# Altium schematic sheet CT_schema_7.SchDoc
size 274 x 160 mm
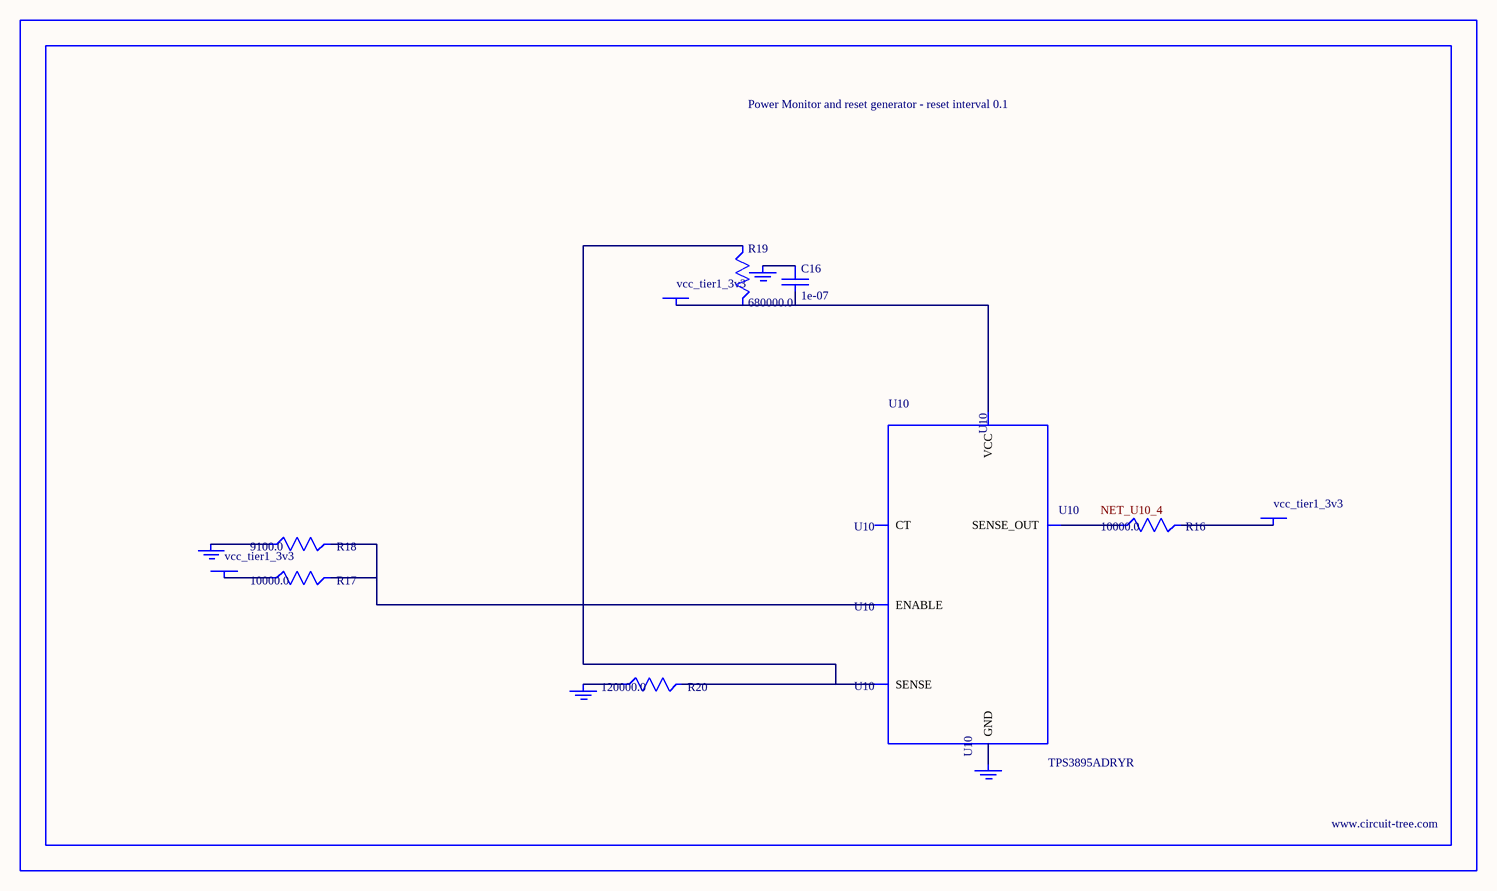
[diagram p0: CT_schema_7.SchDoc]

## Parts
BORDER6  (no value)
C16  1e-07  [C0402]
GND_INSTANCE_6_0  (no value)
GND_INSTANCE_6_1  (no value)
GND_INSTANCE_6_2  (no value)
GND_INSTANCE_6_3  (no value)
POWER_INSTANCE_6_0  vcc_tier1_3v3
POWER_INSTANCE_6_1  vcc_tier1_3v3
POWER_INSTANCE_6_2  vcc_tier1_3v3
R16  10000.0  [R0603]
R17  10000.0  [R0603]
R18  9100.0  [R0603]
R19  680000.0  [R0603]
R20  120000.0  [R0603]
U10  TPS3895ADRYR  [SON-6]

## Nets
NetC16_1: C16.1 GND_INSTANCE_6_2.0(GND)
NetC16_2: C16.2 POWER_INSTANCE_6_2.0(PWR) R19.2 U10.6(VCC)
NetGND_INSTANCE_6_0_0: GND_INSTANCE_6_0.0(GND) R18.1
NetGND_INSTANCE_6_1_0: GND_INSTANCE_6_1.0(GND) R20.1
NetGND_INSTANCE_6_3_0: GND_INSTANCE_6_3.0(GND) U10.2(GND)
NetPOWER_INSTANCE_6_0_0: POWER_INSTANCE_6_0.0(PWR) R17.1
NetPOWER_INSTANCE_6_1_0: POWER_INSTANCE_6_1.0(PWR) R16.2
NetR16_1: R16.1 U10.4(SENSE_OUT)
NetR17_2: R17.2 R18.2 U10.1(ENABLE)
NetR19_1: R19.1 R20.2 U10.3(SENSE)

Not connected (* = marked no-connect by the designer): U10 5(CT)

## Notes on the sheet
- Labels drawn without touching a wire or pin: NET_U10_4

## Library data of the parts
BORDER6 = BORDER_PAGE6
C16 = C0402C104K3RACTU
GND_INSTANCE_6_0-GND_INSTANCE_6_3 = GND
POWER_INSTANCE_6_0-POWER_INSTANCE_6_2 = PWR
R16 R17 = RC0603JR-0710KL
R18 = RC0603JR-079K1L
R19 = RC0603JR-07680KL
R20 = RC0603JR-07120KL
